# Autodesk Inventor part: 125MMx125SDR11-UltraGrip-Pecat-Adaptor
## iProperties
Created: 2012-05
Part Number: 125MMx125SDR11-UltraGrip-Pecat-Adaptor
Document SubType Name: Modeling
Designer: D Cole
Density: 1 g/cm^3
Author: D Cole
